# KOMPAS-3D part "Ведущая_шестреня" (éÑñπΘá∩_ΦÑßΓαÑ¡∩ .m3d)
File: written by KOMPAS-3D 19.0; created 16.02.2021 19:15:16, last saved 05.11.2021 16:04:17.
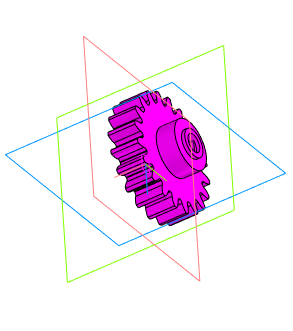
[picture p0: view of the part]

Document properties: Автор: Agent Smith; Полное имя файла: D:\3D_print\3D проекты Компас 3D\Халява Projects 5\Ведущая_шестреня .m3d

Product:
- Part/product: Ведущая_шестреня
    Материал: АБС 0603Т ТУ 2214-019-002 03521-96 (density 0 kg/m3)

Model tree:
1. ЛСК (Шестерня цилиндрическая с внешними зубьями):1  (with: Шестерня цилиндрическая с внешними зубьями:1, Плоскость XY, Плоскость ZX, Плоскость ZY, Ось X, Ось Y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)  (labels: &Фаска (Шестерня цилиндрическая с внешними зубьями):1)
     Ось X. X = 1; Ось Y. Y = 1; Ось Z. Z = 1; Угол 1 = 360
2. Эскиз для винтовой линии (Шестерня цилиндрическая с внешними зубьями):1  (with: Винтовая линия (Шестерня цилиндрическая с внешними зубьями):1, Шестерня цилиндрическая с внешними зубьями:1, Впадина прямая (Шестерня цилиндрическая с внешними зубьями):1, Впадина косая (Шестерня цилиндрическая с внешними зубьями):1, Массив впадин (Шестерня цилиндрическая с внешними зубьями):1)  (2 pattern instances)
     Число витков = 0.00742627; Высота = -2.15631; Смещение 2 = 8
3. Впадина прямая (Шестерня цилиндрическая с внешними зубьями):1  (with: Массив впадин (Шестерня цилиндрическая с внешними зубьями):1, Шестерня цилиндрическая с внешними зубьями:1)  (20 pattern instances)
     N 1 = 1; Шаг 1 = 1; Номер 1 = 1
4. Впадина косая (Шестерня цилиндрическая с внешними зубьями):1  (with: Винтовая линия (Шестерня цилиндрическая с внешними зубьями):1)
     N 1 = 1; Шаг 1 = 1; Номер 1 = 1
5. Шестерня цилиндрическая с внешними зубьями:1
6. Эскиз:5  (with: Цилиндр (Шестерня цилиндрическая с внешними зубьями):1, Впадина прямая (Шестерня цилиндрическая с внешними зубьями):1)
7. Элемент выдавливания:3  (with: Цилиндр (Шестерня цилиндрическая с внешними зубьями):1)
     Расстояние 2 = 8
8. Эскиз:6  (with: Цилиндр (Шестерня цилиндрическая с внешними зубьями):1, Элемент выдавливания:3)
9. Элемент выдавливания:6  (with: Элемент выдавливания:4)  (labels: 28BYJ-48_Motor)
     Расстояние 1 = 5.5
10. Эскиз:7  (with: Элемент выдавливания:6)
11. Элемент выдавливания:8  (labels: АБС 0603Т ТУ 2214-019-002 03521-96)
     Расстояние 1 = 1

Expressions: (VGExtS_1_z*VGExtS_1_M)/COSD(VGExtS_1_Beta); 360/VGExtS_1_z
Referenced files in D:\3D_print\3D проекты Компас 3D\Редуктор (Снова)\: Намоточный станок (Projects 6).a3d
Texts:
  SHAFT3D
  Количество отображаемых зубьев
  Угол наклона линии зубьев
  Шаг по кольцевому направлению
  (VGExtS_1_Beta>0)?(M_PI*VGExtS_1_z*VGExtS_1_M/SIND(VGExtS_1_Beta)):1000
  (VGExtS_1_Da<=0||VGExtS_1_Da>5e+7)?25:VGExtS_1_Da
  (VGExtS_1_H<=0||VGExtS_1_H>5e+7)?25:VGExtS_1_H
  VGExtS_1_zz<VGExtS_1_z?(VGExtS_1_zz+1):VGExtS_1_z
  (VGExtS_1_zz<=0||VGExtS_1==1)||(VGExtS_1_Beta>0)?1:0
  (VGExtS_1_zz<=0||VGExtS_1==1)||(VGExtS_1_Beta<=0)?1:0
  (VGExtS_1==1)||(VGExtS_1_Beta<=0)?1:0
